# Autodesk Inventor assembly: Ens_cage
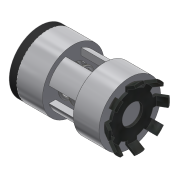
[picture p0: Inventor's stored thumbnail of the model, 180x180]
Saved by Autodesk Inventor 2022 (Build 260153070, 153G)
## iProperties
Created: 2018-06
Part Number: Ens_cage
Material: Générique
Document SubType Name: Assembly
Designer: Fabian Perrée
Author: Fabian Perrée
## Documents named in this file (5)
- C:\Users\Fabian\Google Drive\01_Giup\01_Clients\07_ENI\Manuscrit\Fichiers_exercice\Chapitre_06\Exercice_de_fin_de_chapitre\Exercice_fin_de_chapitre_solution\Ens_cage.iam
- C:\Users\Fabian\Google Drive\01_Giup\01_Clients\07_ENI\Manuscrit\Fichiers_exercice\Chapitre_06\Exercice_de_fin_de_chapitre\Composants\Bouchon.ipt
- C:\Users\Fabian\Google Drive\01_Giup\01_Clients\07_ENI\Manuscrit\Fichiers_exercice\Chapitre_06\Exercice_de_fin_de_chapitre\Composants\Rondelle.ipt
- C:\Users\Fabian\Google Drive\01_Giup\01_Clients\07_ENI\Manuscrit\Fichiers_exercice\Chapitre_06\Exercice_de_fin_de_chapitre\Composants\Cage.ipt
- C:\Users\Fabian\Google Drive\01_Giup\01_Clients\07_ENI\Manuscrit\Fichiers_exercice\Chapitre_06\Exercice_de_fin_de_chapitre\Composants\Ressort de compression11.ipt
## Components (4 placed, 4 different names)
1. Bouchon:1
2. Rondelle:1
3. Cage:1
4. Ressort de compression1:1
